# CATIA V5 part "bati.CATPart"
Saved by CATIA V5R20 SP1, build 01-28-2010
Part number: bati
Publications: "Frontière.3", "Frontière.4", "Frontière.9", "Frontière.10"
Bounding box of the stored display mesh (mm): x -87 to 24, y -78.739 to 415, z -297.725 to 20
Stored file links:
  C:\Users\Fabien-port\Desktop\test\bati.CATPart
  C:\Users\Fabien-port\Desktop\test\mecanisme_a_coulisseau.CATProduct
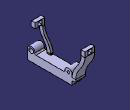
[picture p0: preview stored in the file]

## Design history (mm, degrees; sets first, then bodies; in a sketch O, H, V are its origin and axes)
External parameters (linked from other documents)
  External.largeur_guide_a = 30 mm
  External.hauteur_guide_a = 40 mm
  External.epaisseur_bielle = 8 mm
  External.cote_coulisseau = 30 mm
  External.entraxe_manivelle = 70 mm
  External.rayon_cylindre_bielle = 10 mm
Set1
  Plane1 "Plan_ref": linked copy from another document
  Point1 "Point_ref": linked copy from another document
  Point2 "Point_a2": linked copy from another document
  Plane2 "Plan_ortho_ref": linked copy from another document
  Plane3 "Plan_ortho_construction_bati_bis": linked copy from another document
  Plane4 "Plan_decalage": linked copy from another document
  Point3 "PointA": linked copy from another document
  Point4 "PointD": linked copy from another document
Set2
  Boundary1: Boundary {extract ExtractElem face of Pad6 from Sketch8.L1}
  Boundary2: Boundary {extract ExtractElem face of Pad4}
  Boundary3: Boundary {extract ExtractElem end face of Pad7}
  Boundary4: Boundary {extract ExtractElem end face of Pad8}
Body1 (main body)
  Sketch1 on Plane1, origin (0, 0, 0), H (0, 1, 0), V (0, 0, 1)
    line L1 (-15, 20) -> (15, 20)
    line L2 (15, 20) -> (15, -20)
    line L3 (15, -20) -> (-15, -20)
    line L4 (-15, -20) -> (-15, 20)
    reference projected point E1 (0, 0) from Point1
    reference projected point E2 (0, 0) from Point1
    length L3 = 30 {= External.largeur_guide_a}
    length L4 = 40 {= External.hauteur_guide_a}
    distance L3 E1 = 20 {= External.hauteur_guide_a /2}
    distance L2 E2 = 15 {= External.largeur_guide_a /2}
    horizontal: L1 H, L3 H
    vertical: L2 V, L4 V
  Pad1: profile Sketch1, direction (1, 0, 0), length 24 {= 3*External.epaisseur_bielle}
  Sketch2 on Plane1, origin (0, 0, 0), H (0, 1, 0), V (0, 0, 1)
    line L1 (385, 20) -> (415, 20)
    line L2 (415, 20) -> (415, -20)
    line L3 (415, -20) -> (385, -20)
    line L4 (385, -20) -> (385, 20)
    reference projected point E1 (400, 0) from Point2
    reference projected point E2 (400, 0) from Point2
    length L1 = 30 {= External.largeur_guide_a}
    length L2 = 40 {= External.hauteur_guide_a}
    distance E1 L2 = 15 {= External.largeur_guide_a /2}
    distance L1 E2 = 20 {= External.hauteur_guide_a /2}
    horizontal: L1 H, L3 H
    vertical: L2 V, L4 V
  Pad2: profile Sketch2, direction (1, 0, 0), length 24 {= 3*External.epaisseur_bielle}
  Sketch3 on Plane2, origin (0, 0, 0), H (-1, 0, 0), V (0, 0, 1)
    line L1 (0, 15) -> (0, 20)
    line L2 (0, 20) -> (54, 20)
    line L3 (54, 20) -> (54, -20)
    line L4 (54, -20) -> (0, -20)
    point P5 (0, -20)
    line L5 (0, -20) -> (0, -15)
    line L6 (0, -15) -> (30, -15)
    line L7 (30, -15) -> (30, 15)
    line L8 (30, 15) -> (0, 15)
    reference projected point E1 (0, 0) from Point1
    reference projected point E2 (0, 0) from Point1
    length L7 = 30 {= External.cote_coulisseau}
    length L6 = 30 {= External.cote_coulisseau}
    length L1 = 5 {= (External.hauteur_guide_a -External.cote_coulisseau )/2}
    length L3 = 40 {= External.hauteur_guide_a}
    distance L7 L3 = 24 {= 3*External.epaisseur_bielle}
    distance E1 L8 = 15 {= External.cote_coulisseau /2}
    distance E2 L7 = 30 {= External.cote_coulisseau}
    vertical: L1 V, L3 V, L5 V, L7 V
    horizontal: L2 H, L4 H, L6 H, L8 H
    coincidence: P5 L1
  Pad3: profile Sketch3, direction (0, 1, 0), length 15 {= External.largeur_guide_a /2}, mirrored extent
  Sketch4 on Plane3, origin (0, 400, 0), H (-1, 0, 0), V (0, 0, 1)
    line L1 (0, 15) -> (0, 20)
    line L2 (0, 20) -> (54, 20)
    line L3 (54, 20) -> (54, -20)
    line L4 (54, -20) -> (0, -20)
    line L5 (0, -20) -> (0, -15)
    line L6 (0, -15) -> (30, -15)
    line L7 (30, -15) -> (30, 15)
    line L8 (30, 15) -> (0, 15)
    reference projected point E1 (0, 0) from Point2
    reference projected point E2 (0, 0) from Point2
    length L3 = 40 {= External.hauteur_guide_a}
    length L1 = 5 {= (External.hauteur_guide_a -External.cote_coulisseau )/2}
    length L7 = 30 {= External.cote_coulisseau}
    length L8 = 30 {= External.cote_coulisseau}
    length L6 = 30 {= External.cote_coulisseau}
    length L2 = 54 {= External.cote_coulisseau +3*External.epaisseur_bielle}
    distance E1 L8 = 15 {= External.cote_coulisseau /2}
    distance E2 L7 = 30 {= External.cote_coulisseau}
    vertical: L1 V, L3 V, L5 V, L7 V
    horizontal: L2 H, L4 H, L6 H, L8 H
  Pad4: profile Sketch4, direction (0, 1, 0), length 15 {= External.largeur_guide_a /2}, mirrored extent
  Sketch5 on Plane4, origin (-9, 0, 0), H (0, 1, 0), V (0, 0, 1)
    arc A1 centre (-50, -220) radius 28.75 from (-24.2196, -232.7253) to (-77.6926, -227.7253) ccw
    point P1 (-50, -220)
    point P2 (-24.2196, -232.7253)
    point P3 (-77.6926, -227.7253)
    reference projected point E1 (-50, -220) from Point3
    point P4 (-77.6926, -227.7253)
    line L1 (-77.6926, -227.7253) -> (-77.6926, -297.7253)
    line L2 (-77.6926, -297.7253) -> (277.6927, -297.7253)
    line L3 (277.6927, -297.7253) -> (277.6927, -227.7253)
    point P7 (277.6927, -227.7253)
    arc A2 centre (250, -220) radius 28.75 from (277.6926, -227.7253) to (224.2196, -232.7253) ccw
    point P8 (250, -220)
    point P9 (277.6926, -227.7253)
    point P10 (224.2196, -232.7253)
    reference projected point E2 (250, -220) from Point4
    point P11 (-24.2196, -232.7253)
    line L4 (-24.2196, -232.7253) -> (224.2196, -232.7253)
    point P12 (224.2196, -232.7253)
    distance P1 E1 = 0
    radius A1 = 28.75 {= (External.entraxe_manivelle +1.5*External.cote_coulisseau )/4}
    radius A2 = 28.75 {= (External.entraxe_manivelle +1.5*External.cote_coulisseau )/4}
    distance P8 E2 = 0
    distance P3 P4 = 0
    distance P9 P7 = 0
    length L1 = 70
    distance P11 P2 = 0
    distance P10 L4 = 0
    distance P10 P12 = 0
    distance L4 L2 = 65
    length L3 = 70
    vertical: L1 V, L3 V
    horizontal: L2 H, L4 H
  Pad5: profile Sketch5, direction (-1, 0, 0), length 78 {= External.cote_coulisseau +6*External.epaisseur_bielle}
  Fillet1: radius 10, on edge [face of Pad5 from Sketch5.L4 | face of Pad5 from Sketch5.A1]
  Fillet2: radius 10, on edge [face of Pad5 from Sketch5.A2 | face of Pad5 from Sketch5.L4]
  Sketch6 on Plane4, origin (-9, 260, -180), H (0, 1, 0), V (0, 0, 1)
    point P1 (-10, -40)
    reference projected point E1 (-10, -40) from Point4
    coincidence: E1 P1
  Hole1: placed by Sketch6, at (-9, 250, -220) direction (-1, 0, 0), diameter 20 {= External.rayon_cylindre_bielle *2}, through (limit type 3)
  Sketch7 on Plane4, origin (-9, -40, -180), H (0, 1, 0), V (0, 0, 1)
    point P1 (-10, -40)
    reference projected point E1 (-10, -40) from Point3
    coincidence: E1 P1
  Hole2: placed by Sketch7, at (-9, -50, -220) direction (-1, 0, 0), diameter 36 {= External.rayon_cylindre_bielle *1.8*2}, through (limit type 3)
  Sketch8 on face of Pad5 from Sketch5.L3, origin (0, 277.6927, 0), H (-1, 0, 0), V (0, 0, 1)
    line L1 (9, -242.7253) -> (87, -242.7253)
    line L2 (87, -242.7253) -> (87, -262.7253)
    line L3 (87, -262.7253) -> (9, -262.7253)
    line L4 (9, -262.7253) -> (9, -242.7253)
    reference projected line E1 (6, -227.7253) -> (56, -227.7253) from edge [face of Pad5 from Sketch5.L3 | face of Pad5 from Sketch5.A2]
    reference projected line E2 (87, -256.7741) -> (87, -186.7741) from edge [end face of Pad5 | face of Pad5 from Sketch5.L3]
    reference projected line E3 (9, -256.7741) -> (9, -186.7741) from edge [face of Pad5 from Sketch5.L3 | start face of Pad5]
    distance E1 L1 = 15
    distance L2 E2 = 0
    distance L4 E3 = 0
    distance L1 L3 = 20
    horizontal: L1 H, L3 H
    vertical: L2 V, L4 V
  Pad6: profile Sketch8, direction (0, 1, 0), length 30 {= External.largeur_guide_a}
  Fillet3: radius 10, on edge [face of Pad5 from Sketch5.L3 | face of Pad5 from Sketch5.A2]
  Fillet4: radius 10, on edge [face of Pad5 from Sketch5.L3 | face of Pad6 from Sketch8.L3]
  Chamfer1: length 3, angle 45, on edge [face of Pad5 from Sketch5.L2 | face of Pad5 from Sketch5.L3]
  Chamfer2: length 3, angle 45, on edge [face of Pad5 from Sketch5.L1 | face of Pad5 from Sketch5.L2]
  Fillet5: radius 3, on edge [face of Pad5 from Sketch5.A1 | face of Pad5 from Sketch5.L1]
  Loft1: solid, Sections (Boundary1; Boundary2), StartFace face of Pad6 from Sketch8.L1, EndFace face of Pad4
  Chamfer3: length 5, angle 45, on edge [face of Pad6 from Sketch8.L3 | end face of Pad6]
  Sketch9 on face of Pad5 from Sketch5.L4, origin (0, 0, -232.7253), H (1, 0, 0), V (0, 1, 0)
    line L1 (-87, 46.654) -> (-67.5, 46.654)
    line L2 (-67.5, 46.654) -> (-67.5, 16.654)
    line L3 (-67.5, 16.654) -> (-87, 16.654)
    line L4 (-87, 16.654) -> (-87, 46.654)
    reference projected line E1 through (0, -11.346) direction (-1, 0) from axis of face of Fillet1
    reference projected line E2 (-87, 205.148) -> (-87, -45.148) from edge [face of Pad6 | face of Pad5 from Sketch5.L4]
    distance E1 L3 = 28 {= 0.4*External.entraxe_manivelle}
    length L1 = 19.5 {= (External.cote_coulisseau +6*External.epaisseur_bielle )/4}
    length L4 = 30 {= External.largeur_guide_a}
    distance E2 L4 = 0
    horizontal: L1 H, L3 H
    vertical: L2 V, L4 V
  Pad7: profile Sketch9, direction (0, 0, 1), length 8 {= External.epaisseur_bielle}
  Fillet6: radius 3, on edge [face of Pad5 from Sketch5.L4 | face of Pad7 from Sketch9.L1]
  Fillet7: radius 3, on edge [face of Pad5 from Sketch5.L4 | face of Pad7 from Sketch9.L3]
  Sketch10 on face of Pad3, origin (0, 0, -20), H (1, 0, 0), V (0, -1, 0)
    line L1 (-54, 15) -> (-38, 15)
    line L2 (-38, 15) -> (-38, -15)
    line L3 (-38, -15) -> (-54, -15)
    line L4 (-54, -15) -> (-54, 15)
    reference projected line E1 (0, 15) -> (15, 15) from edge [face of Pad3 | face of Pad3]
    reference projected line E2 (-54, 15) -> (-54, -15) from edge [face of Pad3 from Sketch3.L3 | face of Pad3]
    length L2 = 30 {= External.largeur_guide_a}
    length L1 = 16 {= 2*External.epaisseur_bielle}
    distance L1 E1 = 0
    distance L4 E2 = 0
    horizontal: L1 H, L3 H
    vertical: L2 V, L4 V
  Pad8: profile Sketch10, direction (0, 0, -1), length 16 {= 2*External.epaisseur_bielle}
  Loft2: solid, Sections (Boundary3; Boundary4), StartFace end face of Pad7, EndFace end face of Pad8
  Fillet8: radius 4, on edge [face of Pad3 | face of Pad8 from Sketch10.L2]
Relations
  Sketch9.distance(E1 L3) = 0 (deactivated)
